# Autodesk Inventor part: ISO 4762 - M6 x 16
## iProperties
IsCustomPart: 0
Created: 2007-03
Part Number: ISO 4762 - M6 x 16
Material: Stainless Steel, 440C
Description: Hexagon Socket Head Cap Screw
Document SubType Name: Modeling
Standard: ISO 4762
Designer: Admin
Standard Revision: Fourth edition 2004-03-01
Standards Organization: ISO
Language: en-US
Size Designation: M6 x 16
Categories: <MemberInstance><Categories><Category DisplayName="Fasteners" InternalName="e4da775c-781d-43d5-af7c-5136215cf5a6" Mnemonic="FSTN"><Category DisplayName="Bolts"
Density: 1 g/cm^3
Author: Admin
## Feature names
1. Body [Revolution]
2. Slot [Extrusion]
3. Fillet1
4. Chamfer1
5. Fillet2
